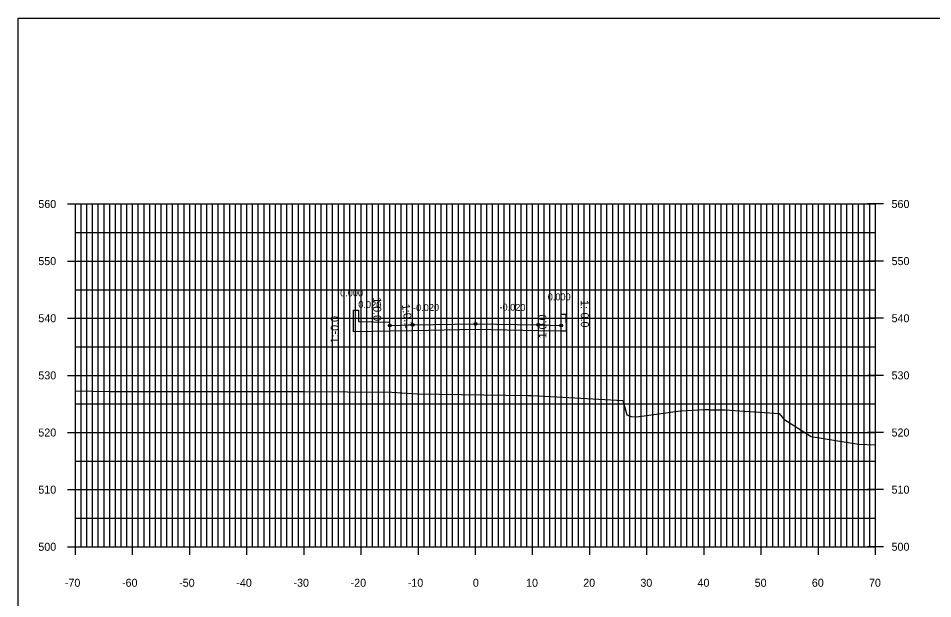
# Model space of a CAD drawing. Extents: x 1509063 to 1512863, y 401160 to 402918.
# Drawn here: x 1511462.7 to 1511622.7, y 402360.5 to 402462.1 of the extents above; entities that cross this region are included whole.
import ezdxf

# ---------------------------------------------------------------- set-up
doc = ezdxf.new("R2010")
doc.units = 0
for name, color, linetype in [('NBL1', 7, 'Continuous'), ('PET_P', 7, 'Continuous'), ('PRC', 7, 'Continuous'), ('PSP_P', 7, 'Continuous'), ('XAX_P', 7, 'Continuous'), ('XAXTIC_P', 7, 'Continuous'), ('XAXTXT_P_T', 7, 'Continuous'), ('XGL_P', 7, 'Continuous'), ('XSL1_P', 7, 'Continuous'), ('XSL1_P_T', 7, 'Continuous'), ('XSL3_P', 7, 'Continuous'), ('XSLOG', 7, 'Continuous')]:
    doc.layers.add(name, color=color, linetype=linetype)

msp = doc.modelspace()

# ---------------------------------------------------------------- linework, layer by layer
at = {"layer": 'NBL1'}
msp.add_lwpolyline([(1511782.73, 402252.08), (1511462.73, 402252.08), (1511462.73, 402462.08), (1511782.73, 402462.08)], close=True, dxfattribs=at)
at = {"layer": 'PET_P'}
for centre in [(1511531.73, 402408.4), (1511553.73, 402408.4)]:
    msp.add_circle(centre, 0.25, dxfattribs=at)
at = {"layer": 'PRC'}
msp.add_circle((1511542.73, 402408.62), 0.25, dxfattribs=at)
at = {"layer": 'PSP_P'}
for centre in [(1511527.73, 402408.32), (1511557.73, 402408.32)]:
    msp.add_circle(centre, 0.25, dxfattribs=at)
at = {"layer": 'XAX_P'}
for p, q in [((1511472.73, 402369.58), (1511472.73, 402429.58)), ((1511542.73, 402369.58), (1511542.73, 402429.58)), ((1511612.73, 402369.58), (1511612.73, 402429.58)), ((1511472.73, 402369.58), (1511612.73, 402369.58))]:
    msp.add_line(p, q, dxfattribs=at)
at = {"layer": 'XAXTIC_P'}
for p, q in [((1511471.33, 402429.58), (1511474.13, 402429.58)), ((1511541.33, 402429.58), (1511544.13, 402429.58)), ((1511614.13, 402429.58), (1511611.33, 402429.58)), ((1511471.33, 402419.58), (1511474.13, 402419.58)), ((1511541.33, 402419.58), (1511544.13, 402419.58)), ((1511614.13, 402419.58), (1511611.33, 402419.58)), ((1511471.33, 402409.58), (1511474.13, 402409.58)), ((1511541.33, 402409.58), (1511544.13, 402409.58)), ((1511614.13, 402409.58), (1511611.33, 402409.58)), ((1511471.33, 402399.58), (1511474.13, 402399.58)), ((1511541.33, 402399.58), (1511544.13, 402399.58)), ((1511614.13, 402399.58), (1511611.33, 402399.58)), ((1511471.33, 402389.58), (1511474.13, 402389.58)), ((1511541.33, 402389.58), (1511544.13, 402389.58)), ((1511614.13, 402389.58), (1511611.33, 402389.58)), ((1511471.33, 402379.58), (1511474.13, 402379.58)), ((1511541.33, 402379.58), (1511544.13, 402379.58)), ((1511614.13, 402379.58), (1511611.33, 402379.58)), ((1511472.73, 402368.18), (1511472.73, 402370.98)), ((1511482.73, 402368.18), (1511482.73, 402370.98)), ((1511492.73, 402368.18), (1511492.73, 402370.98)), ((1511502.73, 402368.18), (1511502.73, 402370.98)), ((1511512.73, 402368.18), (1511512.73, 402370.98)), ((1511522.73, 402368.18), (1511522.73, 402370.98)), ((1511532.73, 402368.18), (1511532.73, 402370.98)), ((1511542.73, 402368.18), (1511542.73, 402370.98)), ((1511552.73, 402368.18), (1511552.73, 402370.98)), ((1511562.73, 402368.18), (1511562.73, 402370.98)), ((1511572.73, 402368.18), (1511572.73, 402370.98)), ((1511582.73, 402368.18), (1511582.73, 402370.98)), ((1511592.73, 402368.18), (1511592.73, 402370.98)), ((1511602.73, 402368.18), (1511602.73, 402370.98)), ((1511612.73, 402368.18), (1511612.73, 402370.98)), ((1511471.33, 402369.58), (1511474.13, 402369.58)), ((1511541.33, 402369.58), (1511544.13, 402369.58)), ((1511614.13, 402369.58), (1511611.33, 402369.58))]:
    msp.add_line(p, q, dxfattribs=at)
at = {"layer": 'XGL_P'}
for p, q in [((1511472.73, 402429.58), (1511612.73, 402429.58)), ((1511472.73, 402369.58), (1511472.73, 402429.58)), ((1511473.73, 402369.58), (1511473.73, 402429.58)), ((1511474.73, 402369.58), (1511474.73, 402429.58)), ((1511475.73, 402369.58), (1511475.73, 402429.58)), ((1511476.73, 402369.58), (1511476.73, 402429.58)), ((1511477.73, 402369.58), (1511477.73, 402429.58)), ((1511478.73, 402369.58), (1511478.73, 402429.58)), ((1511479.73, 402369.58), (1511479.73, 402429.58)), ((1511480.73, 402369.58), (1511480.73, 402429.58)), ((1511481.73, 402369.58), (1511481.73, 402429.58)), ((1511482.73, 402369.58), (1511482.73, 402429.58)), ((1511483.73, 402369.58), (1511483.73, 402429.58)), ((1511484.73, 402369.58), (1511484.73, 402429.58)), ((1511485.73, 402369.58), (1511485.73, 402429.58)), ((1511486.73, 402369.58), (1511486.73, 402429.58)), ((1511487.73, 402369.58), (1511487.73, 402429.58)), ((1511488.73, 402369.58), (1511488.73, 402429.58)), ((1511489.73, 402369.58), (1511489.73, 402429.58)), ((1511490.73, 402369.58), (1511490.73, 402429.58)), ((1511491.73, 402369.58), (1511491.73, 402429.58)), ((1511492.73, 402369.58), (1511492.73, 402429.58)), ((1511493.73, 402369.58), (1511493.73, 402429.58)), ((1511494.73, 402369.58), (1511494.73, 402429.58)), ((1511495.73, 402369.58), (1511495.73, 402429.58)), ((1511496.73, 402369.58), (1511496.73, 402429.58)), ((1511497.73, 402369.58), (1511497.73, 402429.58)), ((1511498.73, 402369.58), (1511498.73, 402429.58)), ((1511499.73, 402369.58), (1511499.73, 402429.58)), ((1511500.73, 402369.58), (1511500.73, 402429.58)), ((1511501.73, 402369.58), (1511501.73, 402429.58)), ((1511502.73, 402369.58), (1511502.73, 402429.58)), ((1511503.73, 402369.58), (1511503.73, 402429.58)), ((1511504.73, 402369.58), (1511504.73, 402429.58)), ((1511505.73, 402369.58), (1511505.73, 402429.58)), ((1511506.73, 402369.58), (1511506.73, 402429.58)), ((1511507.73, 402369.58), (1511507.73, 402429.58)), ((1511508.73, 402369.58), (1511508.73, 402429.58)), ((1511509.73, 402369.58), (1511509.73, 402429.58)), ((1511510.73, 402369.58), (1511510.73, 402429.58)), ((1511511.73, 402369.58), (1511511.73, 402429.58)), ((1511512.73, 402369.58), (1511512.73, 402429.58)), ((1511513.73, 402369.58), (1511513.73, 402429.58)), ((1511514.73, 402369.58), (1511514.73, 402429.58)), ((1511515.73, 402369.58), (1511515.73, 402429.58)), ((1511516.73, 402369.58), (1511516.73, 402429.58)), ((1511517.73, 402369.58), (1511517.73, 402429.58)), ((1511518.73, 402369.58), (1511518.73, 402429.58)), ((1511519.73, 402369.58), (1511519.73, 402429.58)), ((1511520.73, 402369.58), (1511520.73, 402429.58)), ((1511521.73, 402369.58), (1511521.73, 402429.58)), ((1511522.73, 402369.58), (1511522.73, 402429.58)), ((1511523.73, 402369.58), (1511523.73, 402429.58)), ((1511524.73, 402369.58), (1511524.73, 402429.58)), ((1511525.73, 402369.58), (1511525.73, 402429.58)), ((1511526.73, 402369.58), (1511526.73, 402429.58)), ((1511527.73, 402369.58), (1511527.73, 402429.58)), ((1511528.73, 402369.58), (1511528.73, 402429.58)), ((1511529.73, 402369.58), (1511529.73, 402429.58)), ((1511530.73, 402369.58), (1511530.73, 402429.58)), ((1511531.73, 402369.58), (1511531.73, 402429.58)), ((1511532.73, 402369.58), (1511532.73, 402429.58)), ((1511533.73, 402369.58), (1511533.73, 402429.58)), ((1511534.73, 402369.58), (1511534.73, 402429.58)), ((1511535.73, 402369.58), (1511535.73, 402429.58)), ((1511536.73, 402369.58), (1511536.73, 402429.58)), ((1511537.73, 402369.58), (1511537.73, 402429.58)), ((1511538.73, 402369.58), (1511538.73, 402429.58)), ((1511539.73, 402369.58), (1511539.73, 402429.58)), ((1511540.73, 402369.58), (1511540.73, 402429.58)), ((1511541.73, 402369.58), (1511541.73, 402429.58)), ((1511542.73, 402369.58), (1511542.73, 402429.58)), ((1511543.73, 402369.58), (1511543.73, 402429.58)), ((1511544.73, 402369.58), (1511544.73, 402429.58)), ((1511545.73, 402369.58), (1511545.73, 402429.58)), ((1511546.73, 402369.58), (1511546.73, 402429.58)), ((1511547.73, 402369.58), (1511547.73, 402429.58)), ((1511548.73, 402369.58), (1511548.73, 402429.58)), ((1511549.73, 402369.58), (1511549.73, 402429.58)), ((1511550.73, 402369.58), (1511550.73, 402429.58)), ((1511551.73, 402369.58), (1511551.73, 402429.58)), ((1511552.73, 402369.58), (1511552.73, 402429.58)), ((1511553.73, 402369.58), (1511553.73, 402429.58)), ((1511554.73, 402369.58), (1511554.73, 402429.58)), ((1511555.73, 402369.58), (1511555.73, 402429.58)), ((1511556.73, 402369.58), (1511556.73, 402429.58)), ((1511557.73, 402369.58), (1511557.73, 402429.58)), ((1511558.73, 402369.58), (1511558.73, 402429.58)), ((1511559.73, 402369.58), (1511559.73, 402429.58)), ((1511560.73, 402369.58), (1511560.73, 402429.58)), ((1511561.73, 402369.58), (1511561.73, 402429.58)), ((1511562.73, 402369.58), (1511562.73, 402429.58)), ((1511563.73, 402369.58), (1511563.73, 402429.58)), ((1511564.73, 402369.58), (1511564.73, 402429.58)), ((1511565.73, 402369.58), (1511565.73, 402429.58)), ((1511566.73, 402369.58), (1511566.73, 402429.58)), ((1511567.73, 402369.58), (1511567.73, 402429.58)), ((1511568.73, 402369.58), (1511568.73, 402429.58)), ((1511569.73, 402369.58), (1511569.73, 402429.58)), ((1511570.73, 402369.58), (1511570.73, 402429.58)), ((1511571.73, 402369.58), (1511571.73, 402429.58)), ((1511572.73, 402369.58), (1511572.73, 402429.58)), ((1511573.73, 402369.58), (1511573.73, 402429.58)), ((1511574.73, 402369.58), (1511574.73, 402429.58)), ((1511575.73, 402369.58), (1511575.73, 402429.58)), ((1511576.73, 402369.58), (1511576.73, 402429.58)), ((1511577.73, 402369.58), (1511577.73, 402429.58)), ((1511578.73, 402369.58), (1511578.73, 402429.58)), ((1511579.73, 402369.58), (1511579.73, 402429.58)), ((1511580.73, 402369.58), (1511580.73, 402429.58)), ((1511581.73, 402369.58), (1511581.73, 402429.58)), ((1511582.73, 402369.58), (1511582.73, 402429.58)), ((1511583.73, 402369.58), (1511583.73, 402429.58)), ((1511584.73, 402369.58), (1511584.73, 402429.58)), ((1511585.73, 402369.58), (1511585.73, 402429.58)), ((1511586.73, 402369.58), (1511586.73, 402429.58)), ((1511587.73, 402369.58), (1511587.73, 402429.58)), ((1511588.73, 402369.58), (1511588.73, 402429.58)), ((1511589.73, 402369.58), (1511589.73, 402429.58)), ((1511590.73, 402369.58), (1511590.73, 402429.58)), ((1511591.73, 402369.58), (1511591.73, 402429.58)), ((1511592.73, 402369.58), (1511592.73, 402429.58)), ((1511593.73, 402369.58), (1511593.73, 402429.58)), ((1511594.73, 402369.58), (1511594.73, 402429.58)), ((1511595.73, 402369.58), (1511595.73, 402429.58)), ((1511596.73, 402369.58), (1511596.73, 402429.58)), ((1511597.73, 402369.58), (1511597.73, 402429.58)), ((1511598.73, 402369.58), (1511598.73, 402429.58)), ((1511599.73, 402369.58), (1511599.73, 402429.58)), ((1511600.73, 402369.58), (1511600.73, 402429.58)), ((1511601.73, 402369.58), (1511601.73, 402429.58)), ((1511602.73, 402369.58), (1511602.73, 402429.58)), ((1511603.73, 402369.58), (1511603.73, 402429.58)), ((1511604.73, 402369.58), (1511604.73, 402429.58)), ((1511605.73, 402369.58), (1511605.73, 402429.58)), ((1511606.73, 402369.58), (1511606.73, 402429.58)), ((1511607.73, 402369.58), (1511607.73, 402429.58)), ((1511608.73, 402369.58), (1511608.73, 402429.58)), ((1511609.73, 402369.58), (1511609.73, 402429.58)), ((1511610.73, 402369.58), (1511610.73, 402429.58)), ((1511611.73, 402369.58), (1511611.73, 402429.58)), ((1511612.73, 402369.58), (1511612.73, 402429.58)), ((1511472.73, 402424.58), (1511612.73, 402424.58)), ((1511472.73, 402419.58), (1511612.73, 402419.58)), ((1511472.73, 402414.58), (1511612.73, 402414.58)), ((1511472.73, 402409.58), (1511612.73, 402409.58)), ((1511472.73, 402404.58), (1511612.73, 402404.58)), ((1511472.73, 402399.58), (1511612.73, 402399.58)), ((1511472.73, 402394.58), (1511612.73, 402394.58)), ((1511472.73, 402389.58), (1511612.73, 402389.58)), ((1511472.73, 402384.58), (1511612.73, 402384.58)), ((1511472.73, 402379.58), (1511612.73, 402379.58)), ((1511472.73, 402374.58), (1511612.73, 402374.58)), ((1511472.73, 402369.58), (1511612.73, 402369.58))]:
    msp.add_line(p, q, dxfattribs=at)
at = {"layer": 'XSL1_P'}
msp.add_lwpolyline([(1511521.39, 402407.19), (1511521.4, 402411.01), (1511522.23, 402411.01), (1511522.23, 402409.01), (1511527.65, 402408.9), (1511527.73, 402408.32), (1511531.73, 402408.4), (1511542.73, 402408.62), (1511553.73, 402408.4), (1511557.73, 402408.32), (1511557.73, 402410.32), (1511558.56, 402410.32), (1511558.57, 402407.3)], dxfattribs=at)
at = {"layer": 'XSL3_P'}
msp.add_lwpolyline([(1511531.73, 402407.4), (1511527.73, 402407.32), (1511521.39, 402407.19), (1511521.4, 402411.01), (1511522.23, 402411.01), (1511522.23, 402409.01), (1511527.65, 402408.9), (1511527.73, 402408.32), (1511531.73, 402408.4), (1511542.72, 402408.62), (1511553.73, 402408.4), (1511557.73, 402408.32), (1511557.73, 402410.32), (1511558.56, 402410.32), (1511558.57, 402407.3), (1511557.73, 402407.32), (1511553.73, 402407.4), (1511542.72, 402407.62)], close=True, dxfattribs=at)
at = {"layer": 'XSLOG'}
msp.add_lwpolyline([(1511472.73, 402396.87), (1511478.61, 402396.75), (1511503.04, 402396.77), (1511506.36, 402396.76), (1511512.55, 402396.76), (1511528.07, 402396.66), (1511532.52, 402396.35), (1511551.97, 402396.06), (1511552.38, 402396.07), (1511552.77, 402396.03), (1511568.48, 402395.19), (1511569.18, 402392.7), (1511569.98, 402392.4), (1511570.97, 402392.33), (1511578.52, 402393.38), (1511582.9, 402393.58), (1511583.14, 402393.58), (1511583.38, 402393.58), (1511583.62, 402393.58), (1511583.86, 402393.57), (1511584.1, 402393.57), (1511584.33, 402393.57), (1511584.57, 402393.57), (1511584.81, 402393.57), (1511585.04, 402393.56), (1511585.28, 402393.56), (1511585.51, 402393.56), (1511585.75, 402393.56), (1511585.98, 402393.56), (1511586.21, 402393.55), (1511586.44, 402393.55), (1511595.89, 402392.89), (1511596.66, 402391.93), (1511601.44, 402388.86), (1511609.73, 402387.52), (1511612.73, 402387.43)], dxfattribs=at)

# ---------------------------------------------------------------- texts
at = {"layer": 'XAXTXT_P_T'}
for s, p in [('560', (1511466.24, 402428.88)), ('560', (1511615.53, 402428.88)), ('550', (1511466.24, 402418.88)), ('550', (1511615.53, 402418.88)), ('540', (1511466.24, 402408.88)), ('540', (1511615.53, 402408.88)), ('530', (1511466.24, 402398.88)), ('530', (1511615.53, 402398.88)), ('520', (1511466.24, 402388.88)), ('520', (1511615.53, 402388.88)), ('510', (1511466.24, 402378.88)), ('510', (1511615.53, 402378.88)), ('500', (1511466.24, 402368.88)), ('500', (1511615.53, 402368.88)), ('-70', (1511470.88, 402362.58)), ('-60', (1511480.88, 402362.58)), ('-50', (1511490.88, 402362.58)), ('-40', (1511500.88, 402362.58)), ('-30', (1511510.88, 402362.58)), ('-20', (1511520.88, 402362.58)), ('-10', (1511530.88, 402362.58)), ('0', (1511542.27, 402362.58)), ('10', (1511551.58, 402362.58)), ('20', (1511561.58, 402362.58)), ('30', (1511571.58, 402362.58)), ('40', (1511581.58, 402362.58)), ('50', (1511591.58, 402362.58)), ('60', (1511601.58, 402362.58)), ('70', (1511611.58, 402362.58))]:
    msp.add_text(s, height=1.4, dxfattribs=at).set_placement(p)
at = {"layer": 'XSL1_P_T'}
for s, height, rotation, p in [('0.000', 1.2, 360, (1511519.04, 402413.41)), ('0.000', 1.2, 360, (1511519.04, 402413.41)), ('1:0.0', 1.4, 270.0286, (1511524.83, 402413.25)), ('1:0.0', 1.4, 270.0286, (1511524.83, 402413.25)), ('0.000', 1.2, 360, (1511555.37, 402412.72)), ('0.000', 1.2, 360, (1511555.37, 402412.72)), ('0.020', 1.2, 358.8542, (1511522.21, 402411.41)), ('0.020', 1.2, 358.8542, (1511522.21, 402411.41)), ('1:0.1', 1.4, 278.1301, (1511529.83, 402411.96)), ('1:0.1', 1.4, 278.1301, (1511529.83, 402411.96)), ('-0.020', 1.2, 1.1458, (1511531.81, 402410.8)), ('-0.020', 1.2, 1.1458, (1511531.81, 402410.8)), ('-0.020', 1.2, 1.1458, (1511531.81, 402410.8)), ('-0.020', 1.2, 358.8542, (1511546.91, 402410.94)), ('-0.020', 1.2, 358.8542, (1511546.91, 402410.94)), ('-0.020', 1.2, 358.8542, (1511546.91, 402410.94)), ('1:-0.0', 1.4, 270.1899, (1511561.15, 402412.75)), ('1:-0.0', 1.4, 270.1899, (1511561.15, 402412.75)), ('1:-0.0', 1.4, 89.85, (1511518.78, 402405.18)), ('1:-0.0', 1.4, 89.85, (1511518.78, 402405.18)), ('1:0.0', 1.4, 89.9714, (1511555.13, 402406.08)), ('1:0.0', 1.4, 89.9714, (1511555.13, 402406.08))]:
    msp.add_text(s, height=height, rotation=rotation, dxfattribs=at).set_placement(p)

doc.saveas('drawing.dxf')
